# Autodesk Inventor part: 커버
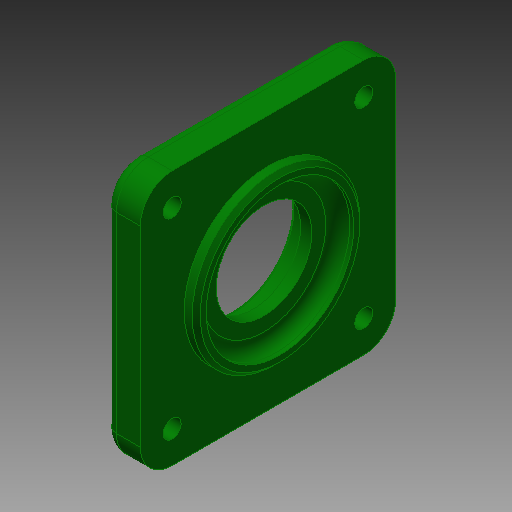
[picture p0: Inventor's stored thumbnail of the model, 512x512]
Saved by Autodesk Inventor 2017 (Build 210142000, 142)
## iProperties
Created: 2019-09
Part Number: 커버
Material: 알루미늄 6061
Document SubType Name: Modeling
Designer: mduedu
Density: 1 g/cm^3
Appearance: 진녹색
Author: mduedu
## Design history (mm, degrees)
sketch "스케치1"
  geometry: L1 (-32, -32)-(32, -32); L2 (32, -32)-(32, 32); L3 (32, 32)-(-32, 32); L4 (-32, 32)-(-32, -32); L5 (-32, -32)-(32, 32); L6 (32, -32)-(-32, 32); 1 further point
  constraints: 12 end point, 2 midpoint, 2 parallel, 1 horizontal, 1 perpendicular
  dimensions: "d44" = 64 distance of L3.end L2.end; "d45" = 64 distance of L2.end L1.end
extrude "돌출1" new body sketch "스케치1" distance "d1" = 9; taper "d2" = 0 deg
sketch "스케치2"
  geometry: C1 r 21 at (0, 0); 1 further point
  constraints: 1 centre point, 1 coincident
  dimensions: "d3" = 42 diameter of C1
extrude "돌출2" join sketch "스케치2" distance "d4" = 3; taper "d5" = 0 deg
hole "구멍1" diameter "d8" = 24; stored, may be unused: countersink angle "d12" = 90 deg, drill point angle "d14" = 118 deg; dims "d9" = 6, "d10" = 30, "d11" = 5.2, "d13" = 8, "d46" = 10, "d47" = 10
hole "구멍2" diameter "d17" = 37; stored, may be unused: countersink angle "d21" = 90 deg, drill point angle "d23" = 0 deg; dims "d15" = 10, "d16" = 10, "d18" = 6, "d19" = 30, "d20" = 5.2, "d22" = 4
fillet "모깎기1" dims "d24" = 3
fillet "모깎기4" dims "d48" = 8
fillet "모깎기2" dims "d25" = 3
chamfer "모따기1" distance "d27" = 0.5; stored, may be unused: second distance "d28" = 2, angle "d29" = 30 deg
chamfer "모따기2" distance "d30" = 1; stored, may be unused: second distance "d31" = 2, angle "d32" = 30 deg
sketch "스케치4"
  geometry: A1 r 8 centre (-24, 24) between (-24, 32) and (-32, 24) reference; A2 r 8 centre (24, 24) between (32, 24) and (24, 32) reference; A3 r 8 centre (24, -24) between (24, -32) and (32, -24) reference; A4 r 8 centre (-24, -24) between (-32, -24) and (-24, -32) reference; 5 further points
  constraints: 4 coincident
hole "구멍4" sketch "스케치4" at (-24, 24), (24, 24), (24, -24), (-24, -24) diameter "d49" = 4.5; stored, may be unused: countersink angle "d53" = 90 deg, drill point angle "d55" = 118 deg; dims "d50" = 6, "d51" = 8, "d52" = 4.4, "d54" = 8
node "솔리드1"
